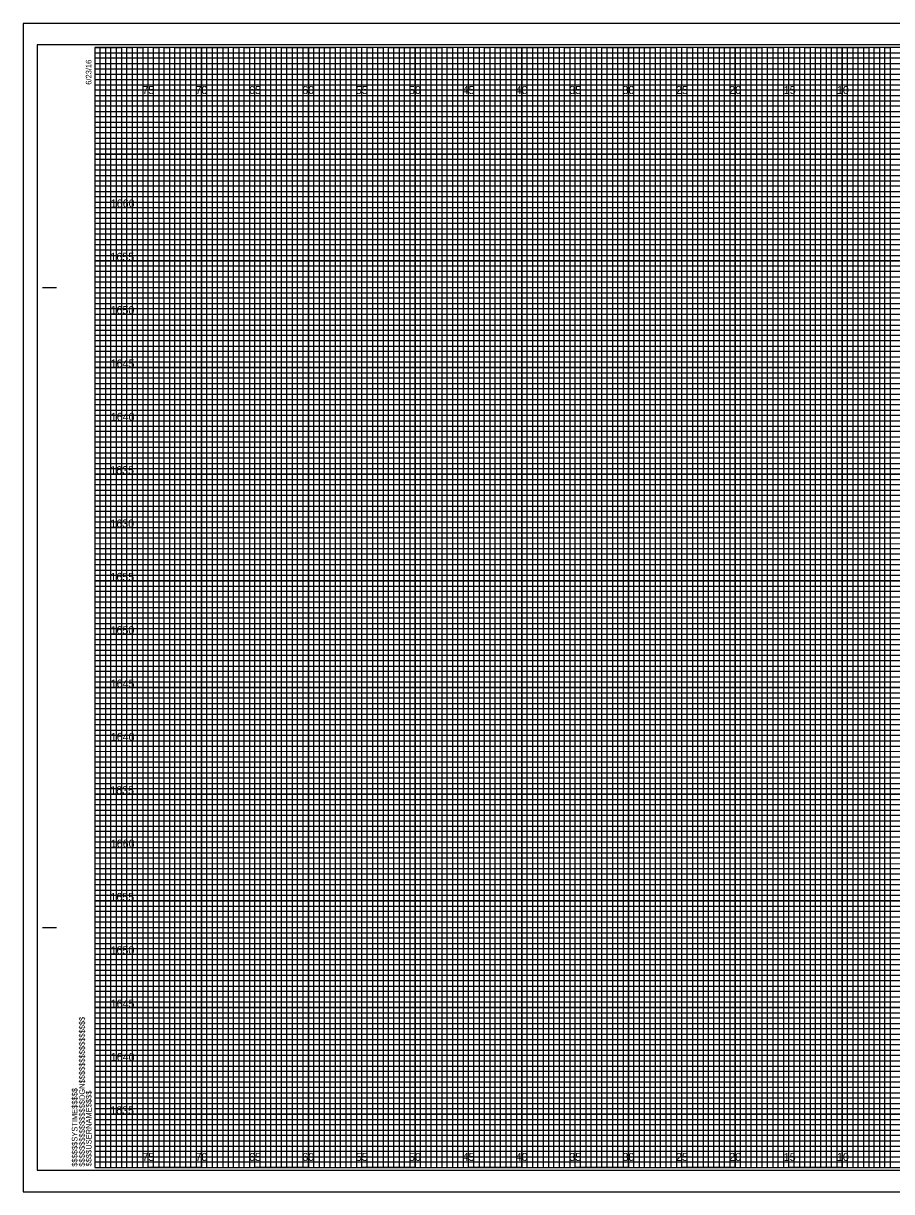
# Model space of a CAD drawing. Extents: x 224 to 392, y 1 to 440.
# Drawn here: x 223.6 to 304.9, y 221 to 330.5 of the extents above; entities that cross this region are included whole.
import ezdxf

# ---------------------------------------------------------------- set-up
doc = ezdxf.new("R2010")
doc.units = 0
for name, color, linetype in [('Prop Grid Mask', 7, 'Continuous'), ('Prop XS Elevation Labels', 7, 'Continuous'), ('Sheet Cross Section CELL', 7, 'Continuous'), ('Sheet Cross Section Grid Major CELL', 7, 'Continuous'), ('Sheet Cross Section Grid Middle CELL', 7, 'Continuous'), ('Sheet Cross Section Grid Minor 1 CELL', 7, 'Continuous'), ('Sheet Cross Section Grid Minor 2 CELL', 7, 'Continuous'), ('Sheet Cutting Line CELL', 7, 'Continuous'), ('Sheet DOT Grid CELL', 7, 'Continuous'), ('Sheet Plot Border Inside CELL', 7, 'Continuous'), ('Sheet Plot Border Outside CELL', 7, 'Continuous')]:
    doc.layers.add(name, color=color, linetype=linetype)

msp = doc.modelspace()

# ---------------------------------------------------------------- linework, layer by layer
at = {"layer": 'Sheet Cross Section CELL'}
for p, q in [((225.36, 305.71), (226.61, 305.71)), ((225.41, 305.71), (226.66, 305.71)), ((225.36, 245.71), (226.61, 245.71)), ((225.41, 245.71), (226.66, 245.71)), ((230.26, 223.21), (230.26, 223.21)), ((230.26, 223.21), (230.26, 223.21)), ((230.26, 223.21), (230.26, 223.21)), ((230.26, 223.21), (230.26, 223.21)), ((230.26, 223.21), (230.26, 223.21)), ((230.26, 223.21), (230.26, 223.21)), ((230.26, 223.21), (230.26, 223.21))]:
    msp.add_line(p, q, dxfattribs=at)
msp.add_lwpolyline([(390.26, 328.21), (230.26, 328.21), (230.26, 223.21), (390.26, 223.21)], close=True, dxfattribs=at)
at = {"layer": 'Sheet Cross Section Grid Major CELL'}
for p, q in [((235.26, 328.21), (230.26, 328.21)), ((235.26, 223.21), (235.26, 328.21)), ((245.26, 328.21), (240.26, 328.21)), ((240.26, 328.21), (240.26, 223.21)), ((245.26, 223.21), (245.26, 328.21)), ((255.26, 328.21), (250.26, 328.21)), ((250.26, 328.21), (250.26, 223.21)), ((255.26, 223.21), (255.26, 328.21)), ((265.26, 328.21), (260.26, 328.21)), ((260.26, 328.21), (260.26, 223.21)), ((265.26, 223.21), (265.26, 328.21)), ((275.26, 328.21), (270.26, 328.21)), ((270.26, 328.21), (270.26, 223.21)), ((275.26, 223.21), (275.26, 328.21)), ((285.26, 328.21), (280.26, 328.21)), ((280.26, 328.21), (280.26, 223.21)), ((285.26, 223.21), (285.26, 328.21)), ((295.26, 328.21), (290.26, 328.21)), ((290.26, 328.21), (290.26, 223.21)), ((295.26, 223.21), (295.26, 328.21)), ((305.26, 328.21), (300.26, 328.21)), ((300.26, 328.21), (300.26, 223.21)), ((240.26, 223.21), (235.26, 223.21)), ((250.26, 223.21), (245.26, 223.21)), ((260.26, 223.21), (255.26, 223.21)), ((270.26, 223.21), (265.26, 223.21)), ((280.26, 223.21), (275.26, 223.21)), ((290.26, 223.21), (285.26, 223.21)), ((300.26, 223.21), (295.26, 223.21))]:
    msp.add_line(p, q, dxfattribs=at)
for points in [[(230.26, 323.21), (390.26, 323.21), (390.26, 318.21), (230.26, 318.21)], [(230.26, 313.21), (390.26, 313.21), (390.26, 308.21), (230.26, 308.21)], [(230.26, 303.21), (390.26, 303.21), (390.26, 298.21), (230.26, 298.21)], [(230.26, 293.21), (390.26, 293.21), (390.26, 288.21), (230.26, 288.21)], [(230.26, 283.21), (390.26, 283.21), (390.26, 278.21), (230.26, 278.21)], [(230.26, 273.21), (390.26, 273.21), (390.26, 268.21), (230.26, 268.21)], [(230.26, 263.21), (390.26, 263.21), (390.26, 258.21), (230.26, 258.21)], [(230.26, 253.21), (390.26, 253.21), (390.26, 248.21), (230.26, 248.21)], [(230.26, 243.21), (390.26, 243.21), (390.26, 238.21), (230.26, 238.21)], [(230.26, 233.21), (390.26, 233.21), (390.26, 228.21), (230.26, 228.21)]]:
    msp.add_lwpolyline(points, dxfattribs=at)
at = {"layer": 'Sheet Cross Section Grid Middle CELL'}
for points in [[(230.26, 328.21), (232.76, 328.21), (232.76, 223.21), (237.76, 223.21), (237.76, 328.21), (242.76, 328.21), (242.76, 223.21), (247.76, 223.21), (247.76, 328.21), (252.76, 328.21), (252.76, 223.21), (257.76, 223.21), (257.76, 328.21), (262.76, 328.21), (262.76, 223.21), (267.76, 223.21), (267.76, 328.21), (272.76, 328.21), (272.76, 223.21), (277.76, 223.21), (277.76, 328.21), (282.76, 328.21), (282.76, 223.21), (287.76, 223.21), (287.76, 328.21), (292.76, 328.21), (292.76, 223.21), (297.76, 223.21), (297.76, 328.21), (302.76, 328.21), (302.76, 223.21), (307.76, 223.21)], [(230.26, 325.71), (367.76, 325.71)], [(230.26, 315.71), (390.26, 315.71), (390.26, 320.71), (230.26, 320.71)], [(230.26, 305.71), (390.26, 305.71), (390.26, 310.71), (230.26, 310.71)], [(230.26, 295.71), (390.26, 295.71), (390.26, 300.71), (230.26, 300.71)], [(230.26, 285.71), (390.26, 285.71), (390.26, 290.71), (230.26, 290.71)], [(230.26, 275.71), (390.26, 275.71), (390.26, 280.71), (230.26, 280.71)], [(230.26, 265.71), (390.26, 265.71), (390.26, 270.71), (230.26, 270.71)], [(230.26, 255.71), (390.26, 255.71), (390.26, 260.71), (230.26, 260.71)], [(230.26, 245.71), (390.26, 245.71), (390.26, 250.71), (230.26, 250.71)], [(230.26, 235.71), (390.26, 235.71), (390.26, 240.71), (230.26, 240.71)], [(230.26, 225.71), (390.26, 225.71), (390.26, 230.71), (230.26, 230.71)]]:
    msp.add_lwpolyline(points, dxfattribs=at)
at = {"layer": 'Sheet Cross Section Grid Minor 1 CELL'}
for p, q in [((230.26, 327.71), (360.26, 327.71)), ((360.26, 327.2), (230.26, 327.2)), ((230.26, 327.2), (230.26, 326.71)), ((230.26, 326.71), (360.26, 326.71)), ((360.26, 326.16), (230.26, 326.16)), ((230.26, 326.16), (230.26, 325.21)), ((230.26, 325.21), (390.26, 325.21))]:
    msp.add_line(p, q, dxfattribs=at)
for points in [[(230.26, 324.71), (365.26, 324.71), (390.26, 324.71), (390.26, 324.21), (230.26, 324.21)], [(230.26, 323.71), (390.26, 323.71), (390.26, 322.71), (230.26, 322.71)], [(230.26, 322.21), (390.26, 322.21), (390.26, 321.71), (230.26, 321.7)], [(230.26, 321.21), (390.26, 321.21), (390.26, 320.21), (230.26, 320.21)], [(230.26, 319.71), (390.26, 319.71), (390.26, 319.21), (230.26, 319.21)], [(230.26, 318.71), (390.26, 318.71), (390.26, 317.71), (230.26, 317.71)], [(230.26, 317.21), (390.26, 317.21), (390.26, 316.71), (230.26, 316.71)], [(230.26, 316.21), (390.26, 316.21), (390.26, 315.21), (230.26, 315.21)], [(230.26, 314.71), (390.26, 314.71), (390.26, 314.21), (230.26, 314.21)], [(230.26, 313.71), (390.26, 313.71), (390.26, 312.71), (230.26, 312.71)], [(230.26, 312.21), (390.26, 312.21), (390.26, 311.71), (230.26, 311.71)], [(230.26, 311.21), (390.26, 311.21), (390.26, 310.19), (390.26, 309.71), (390.26, 309.21), (230.26, 309.21)], [(230.26, 310.21), (390.26, 310.21), (390.26, 309.71), (230.26, 309.71)], [(230.26, 308.71), (390.26, 308.71), (390.26, 307.71), (230.26, 307.73)], [(230.26, 307.73), (390.26, 307.71), (390.26, 307.21), (230.26, 307.21)], [(230.26, 306.71), (390.26, 306.71), (390.26, 306.21), (230.26, 306.21)], [(230.26, 305.21), (390.26, 305.21), (390.26, 304.71), (230.26, 304.71)], [(230.26, 304.21), (390.26, 304.21), (390.26, 303.71), (230.26, 303.71)], [(230.23, 302.66), (390.26, 302.66), (390.26, 302.15), (230.23, 302.15)], [(230.26, 301.71), (390.26, 301.71), (390.26, 301.21), (230.26, 301.21)], [(230.26, 300.21), (390.26, 300.21), (390.26, 299.71), (230.26, 299.71)], [(230.26, 299.21), (390.26, 299.21), (390.26, 298.71), (230.26, 298.71)], [(230.26, 297.71), (390.26, 297.71), (390.26, 297.21), (230.26, 297.21)], [(230.26, 296.71), (390.26, 296.71), (390.26, 296.21), (230.26, 296.21)], [(230.26, 295.21), (390.26, 295.21), (390.26, 294.71), (230.26, 294.71)], [(230.26, 294.21), (390.26, 294.21), (390.26, 293.71), (230.26, 293.71)], [(230.26, 292.71), (390.26, 292.71), (390.26, 292.2), (230.26, 292.21)], [(230.26, 291.71), (390.26, 291.71), (390.26, 291.21), (230.26, 291.21)], [(230.26, 290.21), (390.26, 290.21), (390.26, 289.71), (230.26, 289.71)], [(230.26, 289.21), (390.26, 289.21), (390.26, 288.71), (230.26, 288.71)], [(230.26, 287.71), (390.26, 287.71), (390.26, 287.21), (230.26, 287.21)], [(230.26, 286.71), (390.26, 286.71), (390.26, 286.21), (230.26, 286.21)], [(230.26, 285.21), (390.26, 285.21), (390.26, 284.71), (230.26, 284.71)], [(230.26, 284.21), (390.26, 284.21), (390.26, 283.71), (230.26, 283.71)], [(230.26, 282.71), (390.26, 282.71), (390.26, 282.21), (230.26, 282.21)], [(230.26, 281.71), (390.3, 281.67), (390.26, 281.21), (230.26, 281.21)], [(230.26, 280.21), (390.26, 280.21), (390.26, 279.71), (230.26, 279.71)], [(230.26, 279.21), (390.26, 279.21), (390.26, 278.71), (230.26, 278.71)], [(230.26, 277.71), (390.26, 277.71), (390.26, 277.21), (230.26, 277.21)], [(230.26, 276.71), (390.26, 276.71), (390.26, 276.21), (230.26, 276.21)], [(230.26, 275.21), (390.26, 275.21), (390.26, 274.71), (230.26, 274.71)], [(230.26, 274.21), (390.26, 274.21), (390.26, 273.71), (230.26, 273.71)], [(230.26, 272.71), (390.26, 272.71), (390.26, 272.21), (230.26, 272.21)], [(230.26, 271.71), (390.26, 271.71), (390.26, 271.21), (230.26, 271.21)], [(230.26, 270.21), (390.26, 270.21), (390.26, 269.71), (230.26, 269.71)], [(230.26, 269.21), (390.26, 269.21), (390.26, 268.71), (230.26, 268.71)], [(230.26, 267.71), (390.26, 267.71), (390.26, 267.21), (230.26, 267.21)], [(230.26, 266.71), (390.26, 266.71), (390.26, 266.21), (230.26, 266.21)], [(230.26, 265.21), (390.26, 265.21), (390.26, 264.71), (230.26, 264.71)], [(230.26, 264.21), (390.26, 264.21), (390.26, 263.71), (230.26, 263.71)], [(230.26, 262.71), (390.26, 262.71), (390.26, 262.2), (230.26, 262.21)], [(230.26, 261.71), (390.26, 261.71), (390.26, 261.21), (230.26, 261.21)], [(230.26, 260.21), (390.26, 260.21), (390.26, 259.71), (230.26, 259.71)], [(230.26, 259.21), (390.26, 259.21), (390.26, 258.71), (230.26, 258.71)], [(230.26, 257.71), (390.26, 257.71), (390.26, 257.21), (230.26, 257.21)], [(230.26, 256.71), (390.26, 256.71), (390.26, 256.21), (230.26, 256.21)], [(230.26, 255.21), (390.26, 255.21), (390.26, 254.71), (230.26, 254.71)], [(230.26, 254.21), (390.26, 254.21), (390.26, 253.71), (230.26, 253.71)], [(230.26, 252.71), (390.26, 252.71), (390.26, 252.21), (230.26, 252.21)], [(230.26, 251.71), (390.3, 251.67), (390.26, 251.21), (230.26, 251.21)], [(230.26, 250.21), (390.26, 250.21), (390.26, 249.71), (230.26, 249.71)], [(230.26, 249.21), (390.26, 249.21), (390.26, 248.71), (230.26, 248.71)], [(230.26, 247.71), (390.26, 247.71), (390.26, 247.21), (230.26, 247.21)], [(230.26, 246.71), (390.26, 246.71), (390.26, 246.21), (230.26, 246.21)], [(230.26, 245.21), (390.26, 245.21), (390.26, 244.71), (230.26, 244.71)], [(230.26, 244.21), (390.26, 244.21), (390.26, 243.71), (230.26, 243.71)], [(230.26, 242.71), (390.26, 242.71), (390.26, 242.21), (230.26, 242.21)], [(230.26, 241.71), (390.26, 241.71), (390.26, 241.21), (230.26, 241.21)], [(230.26, 240.21), (390.26, 240.21), (390.26, 239.71), (230.26, 239.71)], [(230.26, 239.21), (390.26, 239.21), (390.26, 238.71), (230.26, 238.71)], [(230.26, 237.71), (390.26, 237.71), (390.26, 237.21), (230.26, 237.21)], [(230.26, 236.71), (390.26, 236.71), (390.26, 236.21), (230.26, 236.21)], [(230.26, 235.21), (390.26, 235.21), (390.26, 234.71), (230.26, 234.71)], [(230.26, 234.21), (390.26, 234.21), (390.26, 233.71), (230.26, 233.71)], [(230.26, 232.71), (390.26, 232.71), (390.26, 232.21), (230.26, 232.21)], [(230.26, 231.71), (390.26, 231.71), (390.26, 231.21), (230.26, 231.21)], [(230.26, 230.21), (390.26, 230.21), (390.26, 229.71), (230.26, 229.71)], [(230.26, 229.21), (390.26, 229.21), (390.26, 228.71), (230.26, 228.71)], [(230.26, 227.71), (390.26, 227.71), (390.26, 227.21), (230.26, 227.21)], [(230.26, 226.71), (390.26, 226.71), (390.26, 226.21), (230.26, 226.21)], [(230.26, 225.21), (390.26, 225.21), (390.26, 224.71), (230.26, 224.71)], [(230.26, 224.21), (390.26, 224.21), (390.26, 223.71), (230.26, 223.71)]]:
    msp.add_lwpolyline(points, dxfattribs=at)
at = {"layer": 'Sheet Cross Section Grid Minor 2 CELL'}
for points in [[(230.26, 223.21), (230.76, 223.21), (230.76, 328.21), (231.26, 328.21), (231.26, 223.21)], [(231.26, 223.21), (231.76, 223.21), (231.76, 328.21), (232.26, 328.21), (232.26, 223.21)], [(232.76, 223.21), (233.26, 223.21), (233.26, 328.21), (233.76, 328.21), (233.76, 223.21)], [(233.76, 223.21), (234.26, 223.21), (234.26, 328.21), (234.76, 328.21), (234.76, 223.21)], [(235.26, 223.21), (235.76, 223.21), (235.76, 328.21), (236.26, 328.21), (236.26, 223.21)], [(236.26, 223.21), (236.76, 223.21), (236.76, 328.21), (237.26, 328.21), (237.26, 223.21)], [(237.76, 223.21), (238.26, 223.21), (238.26, 328.21), (238.76, 328.21), (238.76, 223.21)], [(238.76, 223.21), (239.26, 223.21), (239.26, 328.21), (239.76, 328.21), (239.76, 223.21)], [(240.26, 223.21), (240.76, 223.21), (240.76, 328.21), (241.26, 328.21), (241.26, 223.21)], [(241.26, 223.21), (241.76, 223.21), (241.76, 328.21), (242.26, 328.21), (242.26, 223.21)], [(242.76, 223.21), (243.26, 223.21), (243.26, 328.21), (243.76, 328.21), (243.76, 223.21)], [(243.76, 223.21), (244.26, 223.21), (244.26, 328.21), (244.76, 328.21), (244.76, 223.21)], [(245.26, 223.21), (245.76, 223.21), (245.76, 328.21), (246.26, 328.21), (246.26, 223.21)], [(246.26, 223.21), (246.76, 223.21), (246.76, 328.21), (247.26, 328.21), (247.26, 223.21)], [(247.76, 223.21), (248.26, 223.21), (248.26, 328.21), (248.76, 328.21), (248.76, 223.21)], [(248.76, 223.21), (249.26, 223.21), (249.26, 328.21), (249.76, 328.21), (249.76, 223.21)], [(250.26, 223.21), (250.76, 223.21), (250.76, 328.21), (251.26, 328.21), (251.26, 223.21)], [(251.26, 223.21), (251.76, 223.21), (251.76, 328.21), (252.26, 328.21), (252.26, 223.21)], [(252.76, 223.21), (253.26, 223.21), (253.26, 328.21), (253.76, 328.21), (253.76, 223.21)], [(253.76, 223.21), (254.26, 223.21), (254.26, 328.21), (254.76, 328.21), (254.76, 223.21)], [(255.26, 223.21), (255.76, 223.21), (255.76, 328.21), (256.26, 328.21), (256.26, 223.21)], [(256.26, 223.21), (256.76, 223.21), (256.76, 328.21), (257.26, 328.21), (257.26, 223.21)], [(257.76, 223.21), (258.26, 223.21), (258.26, 328.21), (258.76, 328.21), (258.76, 223.21)], [(258.76, 223.21), (259.26, 223.21), (259.26, 328.21), (259.76, 328.21), (259.76, 223.21)], [(260.26, 223.21), (260.76, 223.21), (260.76, 328.21), (261.26, 328.21), (261.26, 223.21)], [(261.26, 223.21), (261.76, 223.21), (261.76, 328.21), (262.26, 328.21), (262.26, 223.21)], [(262.76, 223.21), (263.26, 223.21), (263.26, 328.21), (263.76, 328.21), (263.76, 223.21)], [(263.76, 223.21), (264.26, 223.21), (264.26, 328.21), (264.76, 328.21), (264.76, 223.21)], [(265.26, 223.21), (265.76, 223.21), (265.76, 328.21), (266.26, 328.21), (266.26, 223.21)], [(266.26, 223.21), (266.76, 223.21), (266.76, 328.21), (267.26, 328.21), (267.26, 223.21)], [(267.76, 223.21), (268.26, 223.21), (268.26, 328.21), (268.76, 328.21), (268.76, 223.21)], [(268.76, 223.21), (269.26, 223.21), (269.26, 328.21), (269.76, 328.21), (269.76, 223.21)], [(270.26, 223.21), (270.76, 223.21), (270.76, 328.21), (271.26, 328.21), (271.26, 223.21)], [(271.26, 223.21), (271.76, 223.21), (271.76, 328.21), (272.26, 328.21), (272.26, 223.21)], [(272.76, 223.21), (273.26, 223.21), (273.26, 328.21), (273.76, 328.21), (273.76, 223.21)], [(273.76, 223.21), (274.26, 223.21), (274.26, 328.21), (274.76, 328.21), (274.76, 223.21)], [(275.26, 223.21), (275.76, 223.21), (275.76, 328.21), (276.26, 328.21), (276.26, 223.21)], [(276.26, 223.21), (276.76, 223.21), (276.76, 328.21), (277.26, 328.21), (277.26, 223.21)], [(277.76, 223.21), (278.26, 223.21), (278.26, 328.21), (278.76, 328.21), (278.76, 223.21)], [(278.76, 223.21), (279.26, 223.21), (279.26, 328.21), (279.76, 328.21), (279.76, 223.21)], [(280.26, 223.21), (280.76, 223.21), (280.76, 328.21), (281.26, 328.21), (281.26, 223.21)], [(281.26, 223.21), (281.76, 223.21), (281.76, 328.21), (282.26, 328.21), (282.26, 223.21)], [(282.76, 223.21), (283.26, 223.21), (283.26, 328.21), (283.76, 328.21), (283.76, 223.21)], [(283.76, 223.21), (284.26, 223.21), (284.26, 328.21), (284.76, 328.21), (284.76, 223.21)], [(285.26, 223.21), (285.76, 223.21), (285.76, 328.21), (286.26, 328.21), (286.26, 223.21)], [(286.26, 223.21), (286.76, 223.21), (286.76, 328.21), (287.26, 328.21), (287.26, 223.21)], [(287.76, 223.21), (288.26, 223.21), (288.26, 328.21), (288.76, 328.21), (288.76, 223.21)], [(288.76, 223.21), (289.26, 223.21), (289.26, 328.21), (289.76, 328.21), (289.76, 223.21)], [(290.26, 223.21), (290.76, 223.21), (290.76, 328.21), (291.26, 328.21), (291.26, 223.21)], [(291.26, 223.21), (291.76, 223.21), (291.76, 328.21), (292.26, 328.21), (292.26, 223.21)], [(292.76, 223.21), (293.26, 223.21), (293.26, 328.21), (293.76, 328.21), (293.76, 223.21)], [(293.76, 223.21), (294.26, 223.21), (294.26, 328.21), (294.76, 328.21), (294.76, 223.21)], [(295.26, 223.21), (295.76, 223.21), (295.76, 328.21), (296.26, 328.21), (296.26, 223.21)], [(296.26, 223.21), (296.76, 223.21), (296.76, 328.21), (297.26, 328.21), (297.26, 223.21)], [(297.76, 223.21), (298.26, 223.21), (298.26, 328.21), (298.76, 328.21), (298.76, 223.21)], [(298.76, 223.21), (299.26, 223.21), (299.26, 328.21), (299.76, 328.21), (299.76, 223.21)], [(300.26, 223.21), (300.76, 223.21), (300.76, 328.21), (301.26, 328.21), (301.26, 223.21)], [(301.26, 223.21), (301.76, 223.21), (301.76, 328.21), (302.26, 328.21), (302.26, 223.21)], [(302.76, 223.21), (303.26, 223.21), (303.26, 328.21), (303.76, 328.21), (303.76, 223.21)], [(303.76, 223.21), (304.26, 223.21), (304.26, 328.21), (304.76, 328.21), (304.76, 223.21)]]:
    msp.add_lwpolyline(points, dxfattribs=at)
at = {"layer": 'Sheet Cutting Line CELL'}
for p, q in [((391.91, 330.46), (223.56, 330.46)), ((223.56, 330.46), (223.56, 220.96)), ((223.56, 220.96), (391.91, 220.96))]:
    msp.add_line(p, q, dxfattribs=at)
at = {"layer": 'Sheet DOT Grid CELL'}
for p, q in [((235.26, 223.21), (235.26, 328.21)), ((240.26, 223.21), (240.26, 328.21)), ((245.26, 223.21), (245.26, 328.21)), ((250.26, 223.21), (250.26, 328.21)), ((255.26, 223.21), (255.26, 328.21)), ((260.26, 223.21), (260.26, 328.21)), ((265.26, 223.21), (265.26, 328.21)), ((270.26, 223.21), (270.26, 328.21)), ((275.26, 223.21), (275.26, 328.21)), ((280.26, 223.21), (280.26, 328.21)), ((285.26, 223.21), (285.26, 328.21)), ((290.26, 223.21), (290.26, 328.21)), ((295.26, 223.21), (295.26, 328.21)), ((300.26, 223.21), (300.26, 328.21)), ((230.26, 323.21), (390.26, 323.21)), ((230.26, 318.21), (390.26, 318.21)), ((230.26, 313.21), (390.26, 313.21)), ((230.26, 308.21), (390.26, 308.21)), ((230.26, 303.21), (390.26, 303.21)), ((230.26, 298.21), (390.26, 298.21)), ((230.26, 293.21), (390.26, 293.21)), ((230.26, 288.21), (390.26, 288.21)), ((230.26, 283.21), (390.26, 283.21)), ((230.26, 278.21), (390.26, 278.21)), ((230.26, 273.21), (390.26, 273.21)), ((230.26, 268.21), (390.26, 268.21)), ((230.26, 263.21), (390.26, 263.21)), ((230.26, 258.21), (390.26, 258.21)), ((230.26, 253.21), (390.26, 253.21)), ((230.26, 248.21), (390.26, 248.21)), ((230.26, 243.21), (390.26, 243.21)), ((230.26, 238.21), (390.26, 238.21)), ((230.26, 233.21), (390.26, 233.21)), ((230.26, 228.21), (390.26, 228.21))]:
    msp.add_line(p, q, dxfattribs=at)
at = {"layer": 'Sheet Plot Border Inside CELL'}
msp.add_lwpolyline([(224.86, 222.96), (391.46, 222.96), (391.46, 328.46), (224.86, 328.46)], close=True, dxfattribs=at)
at = {"layer": 'Sheet Plot Border Outside CELL'}
msp.add_lwpolyline([(223.56, 220.96), (391.91, 220.96), (391.91, 330.46), (223.56, 330.46)], close=True, dxfattribs=at)

# ---------------------------------------------------------------- texts
at = {"layer": 'Prop Grid Mask'}
for s, p in [('75', (234.71, 323.84)), ('70', (239.69, 323.84)), ('65', (244.71, 323.84)), ('60', (249.69, 323.84)), ('55', (254.71, 323.84)), ('50', (259.69, 323.84)), ('45', (264.71, 323.84)), ('40', (269.69, 323.84)), ('35', (274.71, 323.84)), ('30', (279.69, 323.84)), ('25', (284.71, 323.84)), ('20', (289.69, 323.84)), ('15', (294.8, 323.84)), ('10', (299.78, 323.84)), ('75', (234.71, 223.84)), ('70', (239.69, 223.84)), ('65', (244.71, 223.84)), ('60', (249.69, 223.84)), ('55', (254.71, 223.84)), ('50', (259.69, 223.84)), ('45', (264.71, 223.84)), ('40', (269.69, 223.84)), ('35', (274.71, 223.84)), ('30', (279.69, 223.84)), ('25', (284.71, 223.84)), ('20', (289.69, 223.84)), ('15', (294.8, 223.84)), ('10', (299.78, 223.84))]:
    msp.add_text(s, height=0.75, dxfattribs=at).set_placement(p)
at = {"layer": 'Prop XS Elevation Labels'}
for s, p in [('1660', (231.75, 313.21)), ('1655', (231.72, 308.21)), ('1650', (231.73, 303.21)), ('1645', (231.74, 298.21)), ('1640', (231.75, 293.21)), ('1635', (231.7, 288.21)), ('1630', (231.71, 283.21)), ('1655', (231.72, 278.21)), ('1650', (231.73, 273.21)), ('1645', (231.74, 268.21)), ('1640', (231.75, 263.21)), ('1635', (231.7, 258.21)), ('1660', (231.75, 253.21)), ('1655', (231.72, 248.21)), ('1650', (231.73, 243.21)), ('1645', (231.74, 238.21)), ('1640', (231.75, 233.21)), ('1635', (231.7, 228.21))]:
    msp.add_text(s, height=0.75, dxfattribs=at).set_placement(p)
at = {"layer": 'Sheet Cross Section CELL'}
for s, p in [('6/23/16', (229.94, 324.71)), ('$$$$$$$$$$$$$$$$DGN$$$$$$$$$$$$$$$$', (229.32, 223.3)), ('$$$$$$SYSTIME$$$$$', (228.63, 223.3)), ('$$$$USERNAME$$$$', (229.95, 223.33))]:
    msp.add_text(s, height=0.525, rotation=90, dxfattribs=at).set_placement(p)

doc.saveas('drawing.dxf')
